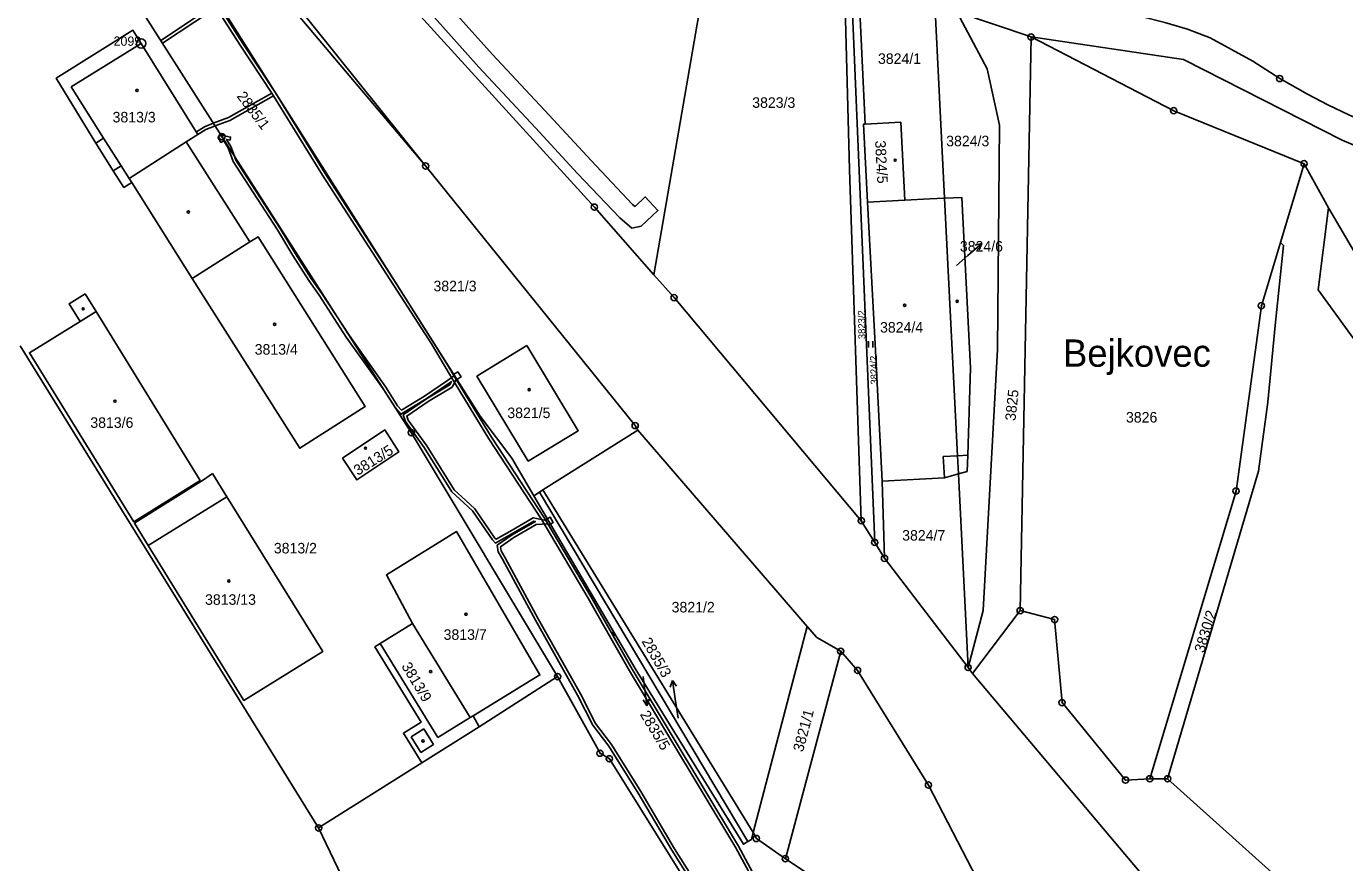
# Model space of a CAD drawing. Extents: x -644096 to -634268, y -1141430 to -1133463.
# Drawn here: x -640699.8 to -640487.2, y -1137506.2 to -1137371.3 of the extents above; entities that cross this region are included whole.
import ezdxf

# ---------------------------------------------------------------- set-up
doc = ezdxf.new("R2010")
doc.units = 0
for name, color, linetype in [('_CIVIL_CONSTRUCTION', 7, 'Continuous'), ('B_Hranice _3D', 7, 'Continuous'), ('M_Svah_Nasyp', 7, 'Continuous'), ('M_Svah_Zarez', 7, 'Continuous'), ('svrsek_osa_sjezdy', 7, 'Continuous'), ('svrsek_osa_VRT', 7, 'Continuous'), ('svrsek_popisy_VRT', 7, 'Continuous'), ('terminal_VRT', 7, 'Continuous')]:
    doc.layers.add(name, color=color, linetype=linetype)

msp = doc.modelspace()

# ---------------------------------------------------------------- linework, layer by layer
at = {"layer": '_CIVIL_CONSTRUCTION'}
for centre, radius in [((-640537.75, -1137373.04), 0.5), ((-640537.75, -1137373.04), 0.0303), ((-640681.33, -1137374.08), 0.75), ((-640681.33, -1137374.08), 0.03), ((-640497.64, -1137379.74), 0.5), ((-640497.64, -1137379.74), 0.0303), ((-640514.74, -1137384.93), 0.5), ((-640514.74, -1137384.93), 0.0303), ((-640668.29, -1137389.12), 0.5), ((-640668.29, -1137389.12), 0.0303), ((-640635.43, -1137393.84), 0.5), ((-640635.43, -1137393.84), 0.0303), ((-640493.7, -1137393.48), 0.5), ((-640493.7, -1137393.48), 0.0303), ((-640608.21, -1137400.49), 0.5), ((-640608.21, -1137400.49), 0.0303), ((-640595.34, -1137415.08), 0.5), ((-640595.34, -1137415.08), 0.0303), ((-640500.59, -1137416.39), 0.5), ((-640500.59, -1137416.39), 0.0303), ((-640637.75, -1137436.87), 0.5), ((-640637.75, -1137436.87), 0.0303), ((-640601.63, -1137435.73), 0.5), ((-640601.63, -1137435.73), 0.0303), ((-640504.68, -1137446.29), 0.5), ((-640504.68, -1137446.29), 0.0303), ((-640565.14, -1137451.08), 0.5), ((-640565.14, -1137451.08), 0.0303), ((-640562.98, -1137454.57), 0.5), ((-640562.98, -1137454.57), 0.0303), ((-640561.4, -1137457.14), 0.5), ((-640561.4, -1137457.14), 0.0303), ((-640539.51, -1137465.59), 0.5), ((-640539.51, -1137465.59), 0.0303), ((-640533.96, -1137467.03), 0.5), ((-640533.96, -1137467.03), 0.0303), ((-640568.46, -1137472.15), 0.5), ((-640568.46, -1137472.15), 0.0303), ((-640565.75, -1137475.24), 0.5), ((-640547.91, -1137474.75), 0.5), ((-640547.91, -1137474.75), 0.0303), ((-640614.14, -1137476.23), 0.5), ((-640614.14, -1137476.23), 0.0303), ((-640565.75, -1137475.24), 0.0303), ((-640532.76, -1137480.43), 0.5), ((-640532.76, -1137480.43), 0.0303), ((-640607.29, -1137488.59), 0.5), ((-640607.29, -1137488.59), 0.0303), ((-640605.78, -1137489.49), 0.5), ((-640605.78, -1137489.49), 0.0303), ((-640554.31, -1137493.73), 0.5), ((-640554.31, -1137493.73), 0.0303), ((-640522.52, -1137492.93), 0.5), ((-640522.52, -1137492.93), 0.0303), ((-640518.59, -1137492.72), 0.5), ((-640518.59, -1137492.72), 0.0303), ((-640515.72, -1137492.72), 0.5), ((-640515.72, -1137492.72), 0.0303), ((-640652.7, -1137500.65), 0.5), ((-640652.7, -1137500.65), 0.0303), ((-640582.07, -1137502.35), 0.5), ((-640582.07, -1137502.35), 0.0303), ((-640577.39, -1137505.61), 0.5), ((-640577.39, -1137505.61), 0.0303)]:
    msp.add_circle(centre, radius, dxfattribs=at)
at = {"layer": 'B_Hranice _3D'}
for points in [[(-640674.56, -1137359.92), (-640665.37, -1137374.35), (-640660.23, -1137382.09), (-640667.22, -1137386.04), (-640669.69, -1137386.94), (-640669.4, -1137387.37), (-640667.02, -1137386.5), (-640659.96, -1137382.52), (-640652.06, -1137395.34), (-640640.59, -1137413.11), (-640634.46, -1137422.53), (-640631.42, -1137427.71), (-640625.24, -1137437.87), (-640616.68, -1137450.95), (-640609.23, -1137463.57), (-640605.76, -1137469.63), (-640602.54, -1137475.28), (-640596.39, -1137485.53), (-640585.37, -1137503.86), (-640580.93, -1137512.11)], [(-640580.51, -1137511.85), (-640584.95, -1137503.6), (-640595.97, -1137485.27), (-640602.1, -1137475.04), (-640605.43, -1137469.19), (-640608.79, -1137463.31), (-640616.24, -1137450.69), (-640624.82, -1137437.61), (-640630.98, -1137427.47), (-640631.52, -1137426.56), (-640631.9, -1137425.91), (-640640.17, -1137412.83), (-640651.64, -1137395.08), (-640659.66, -1137382.05), (-640664.95, -1137374.09), (-640674.08, -1137359.74)], [(-640580.51, -1137511.85), (-640584.95, -1137503.6), (-640595.97, -1137485.27), (-640602.1, -1137475.04), (-640605.19, -1137469.63), (-640604.96, -1137469.53), (-640605.16, -1137469.07), (-640605.43, -1137469.19), (-640608.79, -1137463.31), (-640616.24, -1137450.69), (-640624.82, -1137437.61), (-640630.98, -1137427.47), (-640631.05, -1137427.25), (-640631.52, -1137426.56), (-640631.9, -1137425.91), (-640640.17, -1137412.83), (-640651.64, -1137395.08), (-640659.66, -1137382.05), (-640664.95, -1137374.09), (-640674.08, -1137359.74)], [(-640635.36, -1137368.37), (-640626.86, -1137377.9), (-640617.7, -1137387.71), (-640610.91, -1137395.05), (-640604.1, -1137402.23), (-640602.18, -1137403.86), (-640600.64, -1137403.56), (-640597.95, -1137401.01), (-640600.01, -1137398.83), (-640601.65, -1137400.38), (-640602.04, -1137400.05), (-640608.73, -1137392.99), (-640615.5, -1137385.67), (-640624.64, -1137375.88), (-640633.12, -1137366.37)], [(-640670.3, -1137368.4), (-640678.16, -1137373.6), (-640677.89, -1137374.03), (-640669.98, -1137368.8)], [(-640669.31, -1137368.16), (-640665.37, -1137374.35), (-640660.23, -1137382.09), (-640652.06, -1137395.34), (-640640.59, -1137413.11), (-640634.46, -1137422.53), (-640631.42, -1137427.71), (-640625.24, -1137437.87), (-640616.68, -1137450.95), (-640609.23, -1137463.57)], [(-640589.9, -1137512.5), (-640595.29, -1137504), (-640600.73, -1137494.79), (-640605.45, -1137487.2), (-640608.03, -1137483.79), (-640610.47, -1137479.01), (-640617.26, -1137466.9), (-640622.59, -1137457.05), (-640623.27, -1137455.94), (-640623.35, -1137455.28), (-640621.19, -1137453.8), (-640617.59, -1137451.7), (-640615.64, -1137451.59), (-640615.54, -1137451.76), (-640615.31, -1137451.62), (-640615.82, -1137450.76), (-640616.05, -1137450.9), (-640615.96, -1137451.06), (-640618.07, -1137450.61), (-640621.86, -1137452.81), (-640624.07, -1137454.06), (-640624.28, -1137453.87), (-640627.48, -1137449.19), (-640628.95, -1137447.84), (-640630.81, -1137446.1), (-640635.25, -1137439), (-640638.24, -1137434.85), (-640638.48, -1137434.2), (-640635.03, -1137431.84), (-640631.16, -1137429.51), (-640630.47, -1137428.18), (-640630.79, -1137427.67), (-640631.89, -1137428.47), (-640635.62, -1137430.98), (-640639.32, -1137433.24), (-640639.96, -1137432.55), (-640641.85, -1137429.52), (-640647.79, -1137421.17), (-640642.27, -1137429.8), (-640640.33, -1137432.83), (-640639.42, -1137433.88), (-640635.36, -1137431.4), (-640631.61, -1137428.89), (-640631.27, -1137428.64), (-640631.54, -1137429.15), (-640635.31, -1137431.42), (-640639.08, -1137434), (-640638.68, -1137435.09), (-640635.67, -1137439.28), (-640631.19, -1137446.42), (-640629.29, -1137448.2), (-640627.86, -1137449.51), (-640624.66, -1137454.19), (-640624.15, -1137454.68), (-640621.62, -1137453.25), (-640617.99, -1137451.13), (-640617.73, -1137451.2), (-640621.45, -1137453.38), (-640623.89, -1137455.04), (-640623.75, -1137456.1), (-640623.03, -1137457.29), (-640617.7, -1137467.14), (-640610.91, -1137479.25), (-640608.45, -1137484.05), (-640605.87, -1137487.48), (-640601.15, -1137495.05), (-640595.71, -1137504.26), (-640590.32, -1137512.76)], [(-640609.23, -1137463.57), (-640605.76, -1137469.63), (-640602.54, -1137475.28), (-640596.39, -1137485.53), (-640585.37, -1137503.86), (-640580.93, -1137512.11)]]:
    msp.add_lwpolyline(points, dxfattribs=at)
for points in [[(-640672.42, -1137388.35), (-640672.18, -1137388.76), (-640672.17, -1137388.78), (-640670.89, -1137387.99), (-640669.49, -1137387.4), (-640669.4, -1137387.37), (-640669.69, -1137386.94), (-640671.09, -1137387.53)], [(-640668.98, -1137389.19), (-640668.47, -1137390.05), (-640668, -1137389.77), (-640667.31, -1137390.94), (-640666.48, -1137393.14), (-640659.34, -1137404.17), (-640656.87, -1137408.29), (-640654.3, -1137412.31), (-640652.61, -1137414.68), (-640648.23, -1137421.46), (-640642.27, -1137429.8), (-640647.79, -1137421.17), (-640652.19, -1137414.4), (-640653.88, -1137412.03), (-640656.45, -1137408.03), (-640658.92, -1137403.91), (-640666.04, -1137392.92), (-640666.28, -1137392.26), (-640668.45, -1137388.87)], [(-640668.45, -1137388.87), (-640666.28, -1137392.26), (-640666.85, -1137390.72), (-640667.54, -1137389.57), (-640666.99, -1137389.67), (-640666.9, -1137389.18), (-640667.88, -1137388.99), (-640667.95, -1137388.87), (-640668.17, -1137389), (-640668.3, -1137388.78)], [(-640630.24, -1137427.04), (-640630.91, -1137427.47), (-640630.79, -1137427.67), (-640630.47, -1137428.18), (-640630.38, -1137428.31), (-640629.7, -1137427.89)], [(-640615.82, -1137450.76), (-640615.31, -1137451.62), (-640614.85, -1137451.36), (-640615.36, -1137450.49)]]:
    msp.add_lwpolyline(points, close=True, dxfattribs=at)
at = {"layer": 'M_Svah_Nasyp'}
for p, q in [((-640681.33, -1137374.08), (-640692.63, -1137381.07)), ((-640692.63, -1137381.07), (-640687.39, -1137389.35)), ((-640687.39, -1137389.35), (-640688.64, -1137390.15)), ((-640687.39, -1137389.35), (-640684.56, -1137393.82)), ((-640684.56, -1137393.82), (-640685.82, -1137394.61)), ((-640684.56, -1137393.82), (-640683.26, -1137395.88)), ((-640673.08, -1137411.98), (-640663.8, -1137406.11)), ((-640691.19, -1137418.93), (-640688.61, -1137417.33)), ((-640549.63, -1137440.59), (-640551.91, -1137440.71)), ((-640551.91, -1137440.71), (-640551.73, -1137444.15)), ((-640547.97, -1137440.5), (-640549.63, -1137440.59)), ((-640680.2, -1137455.07), (-640667.51, -1137447.22)), ((-640633.48, -1137486.08), (-640642.79, -1137470.91)), ((-640628.24, -1137482.81), (-640633.48, -1137486.08)), ((-640637.77, -1137485.96), (-640635.71, -1137484.66)), ((-640635.71, -1137484.66), (-640634.14, -1137487.21)), ((-640636.21, -1137488.5), (-640637.77, -1137485.96)), ((-640634.14, -1137487.21), (-640636.21, -1137488.5))]:
    msp.add_line(p, q, dxfattribs=at)
at = {"layer": 'M_Svah_Zarez'}
for centre in [(-640681.99, -1137381.66), (-640559.68, -1137392.92), (-640673.71, -1137401.28), (-640549.67, -1137415.68), (-640690.68, -1137416.9), (-640558.15, -1137416.32), (-640659.8, -1137419.39), (-640618.72, -1137429.94), (-640685.56, -1137431.79), (-640645.13, -1137439.38), (-640667.19, -1137460.8), (-640628.91, -1137466.17), (-640634.61, -1137475.42), (-640635.86, -1137486.61)]:
    msp.add_circle(centre, 0.175, dxfattribs=at)
at = {"layer": 'svrsek_osa_sjezdy'}
for p, q in [((-640563.96, -1137423.12), (-640563.96, -1137422.11)), ((-640563.29, -1137423.12), (-640563.29, -1137422.11))]:
    msp.add_line(p, q, dxfattribs=at)
at = {"layer": 'svrsek_popisy_VRT'}
for p, q in [((-640547.95, -1137408.3), (-640545.69, -1137406.33)), ((-640545.69, -1137406.33), (-640546.77, -1137406.61)), ((-640545.69, -1137406.33), (-640546.11, -1137407.37)), ((-640549.78, -1137409.91), (-640547.95, -1137408.3)), ((-640600.32, -1137476.24), (-640600.11, -1137477.95)), ((-640595.63, -1137476.85), (-640595.97, -1137477.91)), ((-640595.16, -1137479.81), (-640595.63, -1137476.85)), ((-640595.63, -1137476.85), (-640594.98, -1137477.76)), ((-640600.11, -1137477.95), (-640599.74, -1137480.93)), ((-640599.74, -1137480.93), (-640600.36, -1137480)), ((-640599.74, -1137480.93), (-640599.37, -1137479.87)), ((-640594.67, -1137482.93), (-640595.16, -1137479.81))]:
    msp.add_line(p, q, dxfattribs=at)
at = {"layer": 'terminal_VRT'}
for p, q in [((-640598.61, -1137411.41), (-640586.26, -1137339.83)), ((-640562.98, -1137454.57), (-640567.17, -1137355.04)), ((-640565.96, -1137356), (-640564.52, -1137387.09)), ((-640551.72, -1137399.05), (-640553.38, -1137366.07)), ((-640537.75, -1137373.04), (-640549.74, -1137368.98)), ((-640539.51, -1137465.59), (-640537.75, -1137373.04)), ((-640497.53, -1137406.21), (-640493.7, -1137393.48)), ((-640493.7, -1137393.48), (-640489.74, -1137400.58)), ((-640558.12, -1137399.38), (-640564.13, -1137399.7)), ((-640700.83, -1137422.89), (-640652.7, -1137500.65)), ((-640601.2, -1137436.47), (-640616.51, -1137446.11)), ((-640573.87, -1137468.13), (-640601.2, -1137436.47)), ((-640561.4, -1137457.14), (-640561.77, -1137444.69)), ((-640549.48, -1137443.52), (-640547.91, -1137474.75)), ((-640617.04, -1137446.48), (-640617.98, -1137447.08)), ((-640616.51, -1137446.11), (-640617.04, -1137446.48)), ((-640617.04, -1137446.48), (-640583.43, -1137502.83)), ((-640582.58, -1137501.41), (-640616.51, -1137446.11)), ((-640565.14, -1137451.08), (-640562.98, -1137454.57)), ((-640562.98, -1137454.57), (-640561.4, -1137457.14)), ((-640547.91, -1137474.75), (-640561.4, -1137457.14)), ((-640547.2, -1137475.72), (-640539.51, -1137465.59)), ((-640568.46, -1137472.15), (-640577.39, -1137505.61)), ((-640547.91, -1137474.75), (-640547.2, -1137475.72)), ((-640614.14, -1137476.23), (-640626.79, -1137484.34)), ((-640490.94, -1137542.42), (-640547.2, -1137475.72)), ((-640627.76, -1137482.58), (-640626.79, -1137484.34)), ((-640626.79, -1137484.34), (-640636.05, -1137490.17)), ((-640636.05, -1137490.17), (-640652.7, -1137500.65)), ((-640518.59, -1137492.72), (-640515.72, -1137492.72)), ((-640652.7, -1137500.65), (-640631.9, -1137544.15))]:
    msp.add_line(p, q, dxfattribs=at)
for points in [[(-640667.32, -1137333.08), (-640642.36, -1137362.98), (-640608.21, -1137400.49), (-640598.61, -1137411.41)], [(-640635.43, -1137393.84), (-640668.23, -1137352.98), (-640668.58, -1137352.58), (-640678.1, -1137345.74), (-640678.47, -1137345.35), (-640682.23, -1137340.83)], [(-640697.71, -1137342.27), (-640693.32, -1137349.79), (-640668.29, -1137389.12), (-640637.75, -1137436.87), (-640614.14, -1137476.23)], [(-640635.43, -1137393.84), (-640665.69, -1137357.99), (-640668.38, -1137355.38), (-640671.21, -1137354.89), (-640672.5, -1137355.96)], [(-640568.14, -1137354.05), (-640567.03, -1137394.4), (-640565.14, -1137451.08)], [(-640617.98, -1137447.08), (-640621.55, -1137441), (-640626.64, -1137434.23), (-640673.9, -1137359.48)], [(-640553.75, -1137358.58), (-640551.73, -1137359.99), (-640547.18, -1137362.74), (-640541.28, -1137365.76), (-640538.12, -1137366.84), (-640524.13, -1137368.92), (-640519.99, -1137369.74), (-640516.16, -1137370.7), (-640512.5, -1137371.78), (-640508.84, -1137373.18), (-640501.95, -1137376.93), (-640497.64, -1137379.74), (-640493.17, -1137382.26), (-640489.89, -1137383.98), (-640486.51, -1137385.62), (-640483.08, -1137387.13), (-640479.63, -1137388.39), (-640476.26, -1137389.2)], [(-640549.74, -1137368.98), (-640544.85, -1137378.19), (-640542.84, -1137387.24), (-640543.15, -1137423.47), (-640545.48, -1137465.59), (-640547.91, -1137474.75)], [(-640682.85, -1137396.52), (-640684.1, -1137397.31), (-640685.82, -1137394.61), (-640688.64, -1137390.15), (-640695.04, -1137379.69), (-640682.65, -1137371.96), (-640681.33, -1137374.08), (-640672.17, -1137388.75), (-640674.06, -1137389.95)], [(-640493.7, -1137393.48), (-640514.74, -1137384.93), (-640537.75, -1137373.04)], [(-640386.36, -1137505.43), (-640403.74, -1137491.8), (-640423.31, -1137472.2), (-640459.64, -1137425.39), (-640479.82, -1137392.94), (-640487.57, -1137389.69), (-640513.18, -1137376.67), (-640537.75, -1137373.04)], [(-640564.13, -1137399.7), (-640564.78, -1137387.1), (-640564.52, -1137387.09)], [(-640564.52, -1137387.09), (-640558.77, -1137386.79), (-640558.12, -1137399.38)], [(-640682.85, -1137396.52), (-640683.26, -1137395.88), (-640674.06, -1137389.95)], [(-640674.06, -1137389.95), (-640663.8, -1137406.11), (-640662.47, -1137405.27), (-640645.17, -1137432.64), (-640655.74, -1137439.39), (-640673.08, -1137411.98), (-640682.85, -1137396.52)], [(-640601.2, -1137436.47), (-640601.63, -1137435.73), (-640635.43, -1137393.84)], [(-640561.77, -1137444.69), (-640562.93, -1137422.61), (-640564.13, -1137399.7)], [(-640558.12, -1137399.38), (-640554.1, -1137399.17), (-640551.72, -1137399.05)], [(-640551.72, -1137399.05), (-640548.94, -1137398.91), (-640547.51, -1137426.44), (-640547.97, -1137440.5), (-640548.07, -1137443.13), (-640549.48, -1137443.52)], [(-640549.48, -1137443.52), (-640549.63, -1137440.59), (-640551.72, -1137399.05)], [(-640489.74, -1137400.58), (-640491.43, -1137413.85), (-640479.77, -1137429.9), (-640466.9, -1137440.47), (-640468.1, -1137446.74), (-640454.98, -1137457.48), (-640443.19, -1137469.86), (-640428.05, -1137482.66), (-640389.59, -1137511.07)], [(-640489.74, -1137400.58), (-640481.93, -1137413.99), (-640467.46, -1137431.9), (-640451, -1137452.53), (-640422.33, -1137481.27), (-640404.06, -1137493.42), (-640386.36, -1137505.43)], [(-640518.59, -1137492.72), (-640504.68, -1137446.29), (-640500.59, -1137416.39), (-640497.53, -1137406.21)], [(-640497.53, -1137406.21), (-640497.01, -1137406.67), (-640498.36, -1137419.59), (-640499.55, -1137431.96), (-640501.05, -1137443.08), (-640515.72, -1137492.72)], [(-640598.61, -1137411.41), (-640595.34, -1137415.08), (-640565.14, -1137451.08)], [(-640671.81, -1137444.57), (-640682.49, -1137451.28), (-640699.37, -1137423.99), (-640691.19, -1137418.93), (-640692.96, -1137416.08), (-640690.37, -1137414.48), (-640688.61, -1137417.33), (-640671.81, -1137444.57)], [(-640619.1, -1137422.81), (-640610.81, -1137436.57), (-640618.89, -1137441.45), (-640627.17, -1137427.77), (-640619.1, -1137422.81)], [(-640648.87, -1137440.98), (-640642.02, -1137436.42), (-640639.76, -1137439.99), (-640646.53, -1137444.5), (-640648.87, -1137440.98)], [(-640669.8, -1137443.46), (-640667.51, -1137447.22), (-640652.01, -1137472.18), (-640664.76, -1137480.08), (-640680.2, -1137455.07), (-640682.42, -1137451.5), (-640681.91, -1137451.18), (-640671.26, -1137444.46), (-640669.8, -1137443.46)], [(-640561.77, -1137444.69), (-640551.73, -1137444.15), (-640549.48, -1137443.52)], [(-640583.43, -1137502.83), (-640584.16, -1137503.27), (-640601.64, -1137474.91), (-640617.98, -1137447.08)], [(-640637.55, -1137467.66), (-640641.77, -1137459.83), (-640630.47, -1137452.8), (-640616.99, -1137475.95), (-640627.76, -1137482.58)], [(-640539.51, -1137465.59), (-640533.96, -1137467.03), (-640532.76, -1137480.43), (-640522.52, -1137492.93), (-640518.59, -1137492.72)], [(-640636.05, -1137490.17), (-640639.01, -1137485.35), (-640636.13, -1137483.56), (-640643.62, -1137471.45), (-640642.79, -1137470.91), (-640637.55, -1137467.66)], [(-640627.76, -1137482.58), (-640628.24, -1137482.81), (-640637.55, -1137467.66)], [(-640573.87, -1137468.13), (-640574.2, -1137469.39), (-640582.58, -1137501.41)], [(-640568.46, -1137472.15), (-640572.33, -1137469.92), (-640573.87, -1137468.13)], [(-640544.96, -1137511.84), (-640554.31, -1137493.73), (-640565.75, -1137475.24), (-640568.46, -1137472.15)], [(-640614.14, -1137476.23), (-640607.29, -1137488.59), (-640605.78, -1137489.49), (-640588.52, -1137517.2)], [(-640515.72, -1137492.72), (-640499.97, -1137506.88), (-640489.47, -1137516.32)], [(-640582.58, -1137501.41), (-640582.86, -1137502.49), (-640583.43, -1137502.83)], [(-640577.39, -1137505.61), (-640582.07, -1137502.35), (-640582.58, -1137501.41)], [(-640542.54, -1137560.2), (-640554.39, -1137546.81), (-640573.37, -1137508.28), (-640577.39, -1137505.61)]]:
    msp.add_lwpolyline(points, dxfattribs=at)

# ---------------------------------------------------------------- texts
at = {"layer": '_CIVIL_CONSTRUCTION'}
msp.add_text('2099', height=1.5, dxfattribs=at).set_placement((-640685.78, -1137374.46))
at = {"layer": 'svrsek_osa_VRT'}
for s, p in [('3824/1', (-640562.45, -1137377.38)), ('3823/3', (-640582.74, -1137384.47)), ('3813/3', (-640685.94, -1137386.82)), ('3824/3', (-640551.45, -1137390.67)), ('3824/6', (-640549.24, -1137407.66)), ('3821/3', (-640634.17, -1137414.07)), ('3824/4', (-640562.12, -1137420.73)), ('3813/4', (-640663.01, -1137424.29)), ('3813/6', (-640689.53, -1137436.1)), ('3821/5', (-640622.25, -1137434.53)), ('3826', (-640522.44, -1137435.24)), ('3824/7', (-640558.55, -1137454.29)), ('3813/2', (-640659.92, -1137456.36)), ('3813/13', (-640671.02, -1137464.65)), ('3821/2', (-640595.74, -1137465.88)), ('3813/7', (-640632.53, -1137470.3))]:
    msp.add_text(s, height=1.7, dxfattribs=at).set_placement(p)
for s, height, rotation, p in [('2835/1', 1.7, 307, (-640665.99, -1137382.61)), ('3824/5', 1.7, 273, (-640562.92, -1137389.78)), ('3823/2', 1.14, 91, (-640564.48, -1137421.78)), ('3824/2', 1.14, 92, (-640562.46, -1137429.1)), ('3825', 1.7, 84, (-640540.27, -1137435.03)), ('3813/5', 1.7, 32, (-640646.37, -1137443.86)), ('3830/2', 1.7, 73, (-640509.84, -1137472.5)), ('2835/3', 1.7, 300, (-640600.64, -1137470.53)), ('3813/9', 1.7, 301, (-640639.39, -1137474.54)), ('2835/5', 1.7, 301, (-640600.91, -1137482.33)), ('3821/1', 1.7, 75, (-640574.56, -1137488.49))]:
    msp.add_text(s, height=height, rotation=rotation, dxfattribs=at).set_placement(p)
at = {"layer": 'svrsek_popisy_VRT'}
msp.add_text('Bejkovec', height=4.4, dxfattribs=at).set_placement((-640532.61, -1137426.24))

doc.saveas('drawing.dxf')
